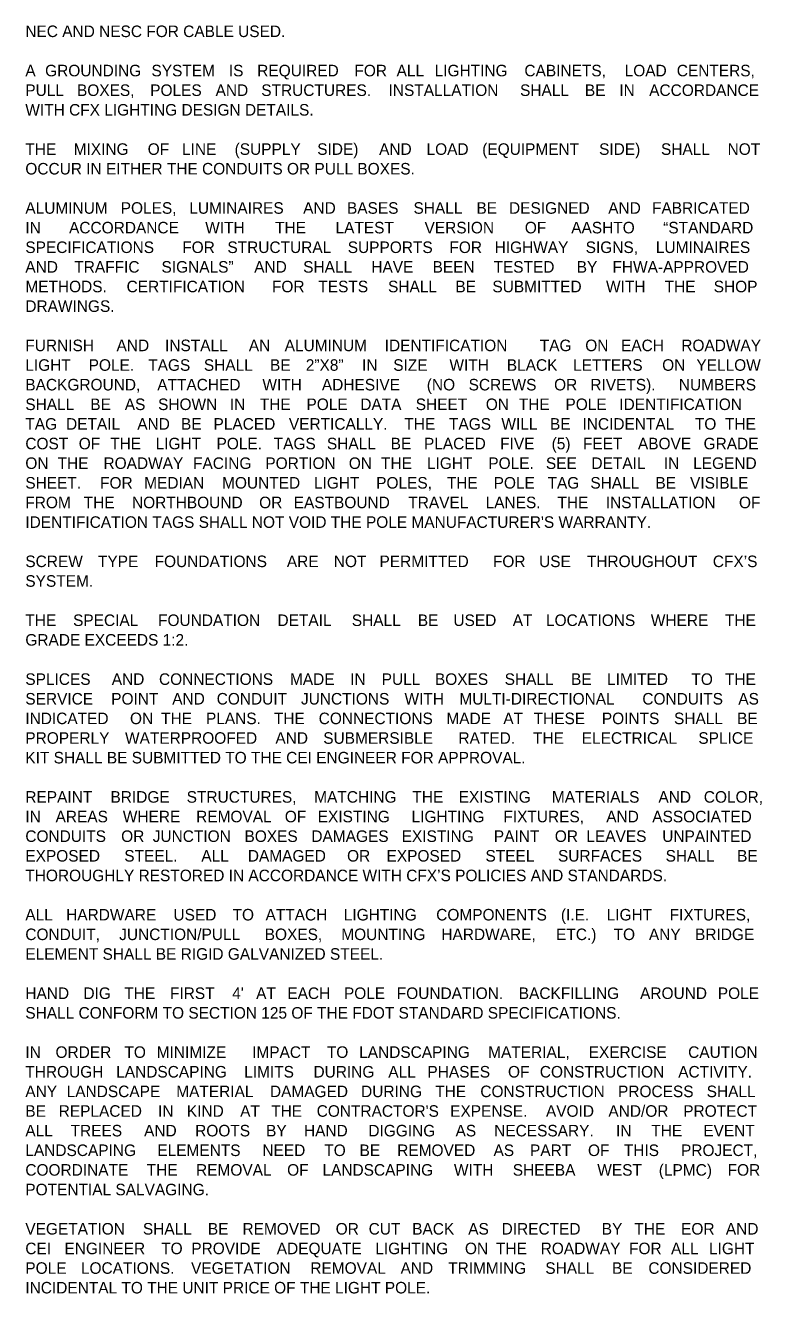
# Model space of a CAD drawing. Extents: x -55 to 2471539, y -90 to 3608906.
# Drawn here: x 568 to 1014, y 8 to 777 of the extents above; entities that cross this region are included whole.
import ezdxf

# ---------------------------------------------------------------- set-up
doc = ezdxf.new("R2010")
doc.units = 0
doc.layers.add('XSCell', color=7, linetype='Continuous')

msp = doc.modelspace()

# ---------------------------------------------------------------- texts
at = {"layer": 'XSCell'}
for s, p in [('NEC AND NESC FOR CABLE USED.', (568.01, 770.14)), ('GROUNDING ', (580.01, 746.34)), ('SYSTEM ', (644.47, 746.34)), ('IS ', (691.38, 746.34)), ('REQUIRED ', (708.58, 746.34)), ('FOR ', (767.49, 746.34)), ('LIGHTING ', (816.15, 746.34)), ('CABINETS, ', (870.55, 746.34)), ('LOAD ', (931.31, 746.34)), ('CENTERS, ', (962.92, 746.34)), ('A ', (568.01, 746.34)), ('ALL ', (793.05, 746.34)), ('PULL ', (568.01, 734.44)), ('BOXES, ', (599.32, 734.44)), ('POLES ', (643.71, 734.44)), ('AND ', (683.35, 734.44)), ('STRUCTURES. ', (711.03, 734.44)), ('INSTALLATION ', (788.2, 734.44)), ('SHALL ', (867.91, 734.44)), ('BE ', (907.21, 734.44)), ('IN ', (928.07, 734.44)), ('ACCORDANCE ', (946.18, 734.44)), ('WITH CFX LIGHTING DESIGN DETAILS.', (568.01, 722.54)), ('THE ', (568.01, 698.74)), ('MIXING ', (597.31, 698.74)), ('OF ', (642.19, 698.74)), ('LINE ', (663, 698.74)), ('(SUPPLY ', (694.88, 698.74)), ('SIDE) ', (744.95, 698.74)), ('AND ', (782.46, 698.74)), ('LOAD ', (811.22, 698.74)), ('(EQUIPMENT ', (844.96, 698.74)), ('SIDE) ', (915.82, 698.74)), ('SHALL ', (953.33, 698.74)), ('NOT ', (993.71, 698.74)), ('OCCUR IN EITHER THE CONDUITS OR PULL BOXES.', (568.01, 686.84)), ('ALUMINUM ', (568.01, 663.04)), ('POLES, ', (625.83, 663.04)), ('LUMINAIRES ', (667.41, 663.04)), ('AND ', (736.42, 663.04)), ('BASES ', (762.98, 663.04)), ('SHALL ', (803.29, 663.04)), ('BE ', (841.48, 663.04)), ('DESIGNED ', (861.21, 663.04)), ('AND ', (921.34, 663.04)), ('FABRICATED ', (947.9, 663.04)), ('IN ', (568.01, 651.14)), ('ACCORDANCE ', (594.51, 651.14)), ('WITH ', (677.06, 651.14)), ('THE ', (719.43, 651.14)), ('LATEST ', (756.05, 651.14)), ('VERSION ', (810.01, 651.14)), ('OF ', (870.8, 651.14)), ('AASHTO ', (898.93, 651.14)), ('“STANDARD ', (954.69, 651.14)), ('SPECIFICATIONS ', (568.01, 639.24)), ('FOR ', (663.12, 639.24)), ('STRUCTURAL ', (690.51, 639.24)), ('SUPPORTS ', (763.45, 639.24)), ('FOR ', (825.09, 639.24)), ('HIGHWAY ', (852.48, 639.24)), ('SIGNS, ', (907.69, 639.24)), ('LUMINAIRES ', (950.21, 639.24)), ('AND ', (568.01, 627.34)), ('TRAFFIC ', (597.7, 627.34)), ('SIGNALS” ', (650.56, 627.34)), ('AND ', (706.75, 627.34)), ('SHALL ', (736.44, 627.34)), ('HAVE ', (777.76, 627.34)), ('BEEN ', (814.87, 627.34)), ('TESTED ', (851.81, 627.34)), ('BY ', (902.26, 627.34)), ('FHWA-APPROVED ', (923.92, 627.34)), ('METHODS. ', (568.01, 615.44)), ('CERTIFICATION ', (629.39, 615.44)), ('FOR ', (717.5, 615.44)), ('TESTS ', (745.65, 615.44)), ('SHALL ', (787.89, 615.44)), ('BE ', (828.73, 615.44)), ('SUBMITTED ', (851.14, 615.44)), ('WITH ', (920.02, 615.44)), ('THE ', (955.54, 615.44)), ('SHOP ', (985.31, 615.44)), ('DRAWINGS.', (568.01, 603.54)), ('FURNISH ', (568.01, 579.74)), ('AND ', (623.29, 579.74)), ('INSTALL ', (652.69, 579.74)), ('AN ', (703.49, 579.74)), ('ALUMINUM ', (725.21, 579.74)), ('IDENTIFICATION ', (785.87, 579.74)), ('TAG ', (879.86, 579.74)), ('ON ', (907.43, 579.74)), ('EACH ', (929.1, 579.74)), ('ROADWAY ', (965.64, 579.74)), ('LIGHT ', (568.01, 567.84)), ('POLE. ', (606.39, 567.84)), ('TAGS ', (642.51, 567.84)), ('SHALL ', (676.24, 567.84)), ('BE ', (716.34, 567.84)), ('2”X8” ', (738.01, 567.84)), ('IN ', (772.11, 567.84)), ('SIZE ', (791.03, 567.84)), ('WITH ', (825.09, 567.84)), ('BLACK ', (859.87, 567.84)), ('LETTERS ', (900.07, 567.84)), ('ON ', (954.05, 567.84)), ('YELLOW ', (974.8, 567.84)), ('BACKGROUND, ', (568.01, 555.94)), ('ATTACHED ', (647.98, 555.94)), ('WITH ', (711.72, 555.94)), ('ADHESIVE ', (747.77, 555.94)), ('(NO ', (811.36, 555.94)), ('SCREWS ', (836.74, 555.94)), ('OR ', (888.54, 555.94)), ('RIVETS). ', (910.5, 555.94)), ('NUMBERS ', (964.15, 555.94)), ('SHALL ', (568.01, 544.04)), ('BE ', (607.37, 544.04)), ('AS ', (628.28, 544.04)), ('SHOWN ', (648.48, 544.04)), ('IN ', (691.99, 544.04)), ('THE ', (710.16, 544.04)), ('POLE ', (738.44, 544.04)), ('DATA ', (771.06, 544.04)), ('SHEET ', (804.66, 544.04)), ('ON ', (847.15, 544.04)), ('THE ', (867.16, 544.04)), ('POLE ', (895.44, 544.04)), ('IDENTIFICATION ', (928.06, 544.04)), ('TAG ', (568.01, 532.14)), ('DETAIL ', (592.69, 532.14)), ('AND ', (635.86, 532.14)), ('BE ', (662.38, 532.14)), ('PLACED ', (682.08, 532.14)), ('VERTICALLY. ', (727.77, 532.14)), ('THE ', (797.76, 532.14)), ('TAGS ', (824.83, 532.14)), ('WILL ', (856.59, 532.14)), ('BE ', (886.05, 532.14)), ('INCIDENTAL ', (905.75, 532.14)), ('TO ', (973.89, 532.14)), ('THE ', (992.12, 532.14)), ('COST ', (568.01, 520.24)), ('OF ', (600.37, 520.24)), ('THE ', (619.44, 520.24)), ('LIGHT ', (647, 520.24)), ('POLE. ', (683.91, 520.24)), ('TAGS ', (718.57, 520.24)), ('SHALL ', (750.83, 520.24)), ('BE ', (789.47, 520.24)), ('PLACED ', (809.66, 520.24)), ('FIVE ', (855.85, 520.24)), ('(5) ', (887.05, 520.24)), ('FEET ', (906.02, 520.24)), ('ABOVE ', (939.36, 520.24)), ('GRADE ', (979.17, 520.24)), ('ON ', (568.01, 508.34)), ('THE ', (587.57, 508.34)), ('ROADWAY ', (615.39, 508.34)), ('FACING ', (669.69, 508.34)), ('PORTION ', (713.51, 508.34)), ('ON ', (764.09, 508.34)), ('THE ', (783.65, 508.34)), ('LIGHT ', (811.48, 508.34)), ('POLE. ', (848.66, 508.34)), ('SEE ', (883.58, 508.34)), ('DETAIL ', (911.18, 508.34)), ('IN ', (955.12, 508.34)), ('LEGEND ', (972.84, 508.34)), ('SHEET. ', (568.01, 496.44)), ('FOR ', (613.33, 496.44)), ('MEDIAN ', (640.07, 496.44)), ('MOUNTED ', (687.27, 496.44)), ('LIGHT ', (742.99, 496.44)), ('POLES, ', (780.69, 496.44)), ('THE ', (823.52, 496.44)), ('POLE ', (851.88, 496.44)), ('TAG ', (884.57, 496.44)), ('SHALL ', (910.54, 496.44)), ('BE ', (949.98, 496.44)), ('VISIBLE ', (970.96, 496.44)), ('FROM ', (568.01, 484.54)), ('THE ', (603.39, 484.54)), ('NORTHBOUND ', (632.65, 484.54)), ('OR ', (709.75, 484.54)), ('EASTBOUND ', (730.69, 484.54)), ('TRAVEL ', (800.16, 484.54)), ('LANES. ', (847.03, 484.54)), ('THE ', (890.59, 484.54)), ('INSTALLATION ', (919.86, 484.54)), ('OF ', (1000.61, 484.54)), ("IDENTIFICATION TAGS SHALL NOT VOID THE POLE MANUFACTURER'S WARRANTY.", (568.01, 472.64)), ('SCREW ', (568.01, 448.84)), ('TYPE ', (612.05, 448.84)), ('FOUNDATIONS ', (646.38, 448.84)), ('ARE ', (726.54, 448.84)), ('NOT ', (755, 448.84)), ('PERMITTED ', (782.71, 448.84)), ('FOR ', (851.45, 448.84)), ('USE ', (879.44, 448.84)), ('THROUGHOUT ', (908.4, 448.84)), ('CFX’S ', (984.76, 448.84)), ('SYSTEM.', (568.01, 436.94)), ('THE ', (568.01, 413.14)), ('SPECIAL ', (596.95, 413.14)), ('FOUNDATION ', (648.45, 413.14)), ('DETAIL ', (720.86, 413.14)), ('SHALL ', (765.91, 413.14)), ('BE ', (805.93, 413.14)), ('USED ', (827.51, 413.14)), ('AT ', (863.48, 413.14)), ('LOCATIONS ', (883.63, 413.14)), ('WHERE ', (947.18, 413.14)), ('THE ', (992.12, 413.14)), ('GRADE EXCEEDS 1:2.', (568.01, 401.24)), ('SPLICES ', (568.01, 377.44)), ('AND ', (620.4, 377.44)), ('CONNECTIONS ', (649.03, 377.44)), ('MADE ', (728.42, 377.44)), ('IN ', (764.98, 377.44)), ('PULL ', (784.04, 377.44)), ('BOXES ', (816.31, 377.44)), ('SHALL ', (858.59, 377.44)), ('BE ', (898.84, 377.44)), ('LIMITED ', (920.65, 377.44)), ('TO ', (971.78, 377.44)), ('THE ', (992.12, 377.44)), ('SERVICE ', (568.01, 365.54)), ('POINT ', (620.07, 365.54)), ('AND ', (657.06, 365.54)), ('CONDUIT ', (684.01, 365.54)), ('JUNCTIONS ', (735.09, 365.54)), ('WITH ', (797.86, 365.54)), ('MULTI-DIRECTIONAL ', (831.11, 365.54)), ('CONDUITS ', (942.04, 365.54)), ('AS ', (1000.2, 365.54)), ('INDICATED ', (568.01, 353.64)), ('ON ', (631.45, 353.64)), ('THE ', (650.33, 353.64)), ('PLANS. ', (677.5, 353.64)), ('THE ', (718.68, 353.64)), ('CONNECTIONS ', (745.84, 353.64)), ('MADE ', (823.22, 353.64)), ('AT ', (857.76, 353.64)), ('THESE ', (876.13, 353.64)), ('POINTS ', (917.5, 353.64)), ('SHALL ', (961.24, 353.64)), ('BE ', (999.48, 353.64)), ('PROPERLY ', (568.01, 341.74)), ('WATERPROOFED ', (628.45, 341.74)), ('AND ', (719.6, 341.74)), ('SUBMERSIBLE ', (748.61, 341.74)), ('RATED. ', (830.55, 341.74)), ('THE ', (875.77, 341.74)), ('ELECTRICAL ', (905.32, 341.74)), ('SPLICE ', (975.98, 341.74)), ('KIT SHALL BE SUBMITTED TO THE CEI ENGINEER FOR APPROVAL.', (568.01, 329.84)), ('REPAINT ', (568.01, 306.04)), ('BRIDGE ', (619.62, 306.04)), ('STRUCTURES, ', (665.82, 306.04)), ('MATCHING ', (743.13, 306.04)), ('THE ', (802.64, 306.04)), ('EXISTING ', (830.7, 306.04)), ('MATERIALS ', (887.2, 306.04)), ('AND ', (951.78, 306.04)), ('COLOR, ', (979.3, 306.04)), ('IN ', (568.01, 294.14)), ('AREAS ', (586.33, 294.14)), ('WHERE ', (627.11, 294.14)), ('REMOVAL ', (671.54, 294.14)), ('OF ', (725.3, 294.14)), ('EXISTING ', (745.24, 294.14)), ('LIGHTING ', (802.12, 294.14)), ('FIXTURES, ', (857.79, 294.14)), ('AND ', (920.15, 294.14)), ('ASSOCIATED ', (948.05, 294.14)), ('CONDUITS ', (568.01, 282.24)), ('OR ', (626.11, 282.24)), ('JUNCTION ', (645.22, 282.24)), ('BOXES ', (700.86, 282.24)), ('DAMAGES ', (741.4, 282.24)), ('EXISTING ', (796.13, 282.24)), ('PAINT ', (852.01, 282.24)), ('OR ', (888.99, 282.24)), ('LEAVES ', (908.1, 282.24)), ('UNPAINTED ', (954.1, 282.24)), ('EXPOSED ', (568.01, 270.34)), ('STEEL. ', (627.98, 270.34)), ('ALL ', (674.69, 270.34)), ('DAMAGED ', (702.88, 270.34)), ('OR ', (763.04, 270.34)), ('EXPOSED ', (786.96, 270.34)), ('STEEL ', (846.94, 270.34)), ('SURFACES ', (890.89, 270.34)), ('SHALL ', (956.14, 270.34)), ('BE ', (999.48, 270.34)), ('THOROUGHLY RESTORED IN ACCORDANCE WITH CFX’S POLICIES AND STANDARDS. ', (568.01, 258.44)), ('ALL ', (568.01, 234.64)), ('HARDWARE ', (592.75, 234.64)), ('USED ', (657.8, 234.64)), ('TO ', (693.63, 234.64)), ('ATTACH ', (713.61, 234.64)), ('LIGHTING ', (761.04, 234.64)), ('COMPONENTS ', (817.08, 234.64)), ('(I.E. ', (892.66, 234.64)), ('LIGHT ', (920.42, 234.64)), ('FIXTURES, ', (958.58, 234.64)), ('CONDUIT, ', (568.01, 222.74)), ('JUNCTION/PULL ', (624.91, 222.74)), ('BOXES, ', (713.12, 222.74)), ('MOUNTING ', (759.53, 222.74)), ('HARDWARE, ', (820.2, 222.74)), ('ETC.) ', (889.76, 222.74)), ('TO ', (924.61, 222.74)), ('ANY ', (946.03, 222.74)), ('BRIDGE ', (973.98, 222.74)), ('ELEMENT SHALL BE RIGID GALVANIZED STEEL.', (568.01, 210.84)), ('HAND ', (568.01, 187.04)), ('DIG ', (603.24, 187.04)), ('THE ', (627.99, 187.04)), ('FIRST ', (655.69, 187.04)), ("4' ", (693.4, 187.04)), ('AT ', (707.92, 187.04)), ('EACH ', (726.83, 187.04)), ('POLE ', (761.14, 187.04)), ('FOUNDATION. ', (793.18, 187.04)), ('BACKFILLING ', (867.11, 187.04)), ('AROUND ', (940.66, 187.04)), ('POLE ', (987.78, 187.04)), ('SHALL CONFORM TO SECTION 125 OF THE FDOT STANDARD SPECIFICATIONS.', (568.01, 175.14)), ('IN ', (568.01, 151.34)), ('ORDER ', (586.31, 151.34)), ('TO ', (628.08, 151.34)), ('MINIMIZE ', (647.66, 151.34)), ('IMPACT ', (705.48, 151.34)), ('TO ', (750.79, 151.34)), ('LANDSCAPING ', (770.36, 151.34)), ('MATERIAL, ', (848.58, 151.34)), ('EXERCISE ', (909.49, 151.34)), ('CAUTION ', (969.8, 151.34)), ('THROUGH ', (568.01, 139.44)), ('LANDSCAPING ', (623.09, 139.44)), ('LIMITS ', (700.68, 139.44)), ('DURING ', (742.68, 139.44)), ('ALL ', (788.03, 139.44)), ('PHASES ', (811.75, 139.44)), ('OF ', (860.6, 139.44)), ('CONSTRUCTION ', (879.89, 139.44)), ('ACTIVITY. ', (963.78, 139.44)), ('ANY ', (568.01, 127.54)), ('LANDSCAPE ', (593.07, 127.54)), ('MATERIAL ', (659.49, 127.54)), ('DAMAGED ', (716.29, 127.54)), ('DURING ', (771.54, 127.54)), ('THE ', (816.47, 127.54)), ('CONSTRUCTION ', (843.83, 127.54)), ('PROCESS ', (927.29, 127.54)), ('SHALL ', (981.03, 127.54)), ('BE ', (568.01, 115.64)), ('REPLACED ', (588.23, 115.64)), ('IN ', (648.46, 115.64)), ('KIND ', (665.93, 115.64)), ('AT ', (698.24, 115.64)), ('THE ', (717.04, 115.64)), ("CONTRACTOR'S ", (744.63, 115.64)), ('EXPENSE. ', (825.54, 115.64)), ('AVOID ', (883.61, 115.64)), ('AND/OR ', (921.45, 115.64)), ('PROTECT ', (966.83, 115.64)), ('ALL ', (568.01, 103.74)), ('TREES ', (595.45, 103.74)), ('AND ', (639.99, 103.74)), ('ROOTS ', (670.96, 103.74)), ('BY ', (713.96, 103.74)), ('HAND ', (736.91, 103.74)), ('DIGGING ', (775.95, 103.74)), ('AS ', (828.8, 103.74)), ('NECESSARY. ', (852.22, 103.74)), ('IN ', (926.06, 103.74)), ('THE ', (947.46, 103.74)), ('EVENT ', (978.98, 103.74)), ('LANDSCAPING ', (568.01, 91.84)), ('ELEMENTS ', (648.02, 91.84)), ('NEED ', (711.71, 91.84)), ('TO ', (749.23, 91.84)), ('BE ', (770.6, 91.84)), ('REMOVED ', (793.44, 91.84)), ('AS ', (851.82, 91.84)), ('PART ', (873.94, 91.84)), ('OF ', (909.09, 91.84)), ('THIS ', (930.81, 91.84)), ('PROJECT, ', (965.48, 91.84)), ('COORDINATE ', (568.01, 79.94)), ('THE ', (641.59, 79.94)), ('REMOVAL ', (671.49, 79.94)), ('OF ', (726.72, 79.94)), ('LANDSCAPING ', (748.13, 79.94)), ('WITH ', (827.84, 79.94)), ('SHEEBA ', (863.49, 79.94)), ('WEST ', (914.73, 79.94)), ('(LPMC) ', (951.99, 79.94)), ('FOR ', (993.73, 79.94)), ('POTENTIAL SALVAGING.', (568.01, 68.04)), ('VEGETATION ', (568.01, 44.24)), ('SHALL ', (639.27, 44.24)), ('BE ', (678.67, 44.24)), ('REMOVED ', (699.63, 44.24)), ('OR ', (756.14, 44.24)), ('CUT ', (776.13, 44.24)), ('BACK ', (802.52, 44.24)), ('AS ', (836.47, 44.24)), ('DIRECTED ', (856.71, 44.24)), ('BY ', (917.44, 44.24)), ('THE ', (937.2, 44.24)), ('EOR ', (965.52, 44.24)), ('AND ', (992.65, 44.24)), ('CEI ', (568.01, 32.34)), ('ENGINEER ', (591.75, 32.34)), ('TO ', (650.35, 32.34)), ('PROVIDE ', (668.61, 32.34)), ('ADEQUATE ', (720.42, 32.34)), ('LIGHTING ', (780.17, 32.34)), ('ON ', (834.49, 32.34)), ('THE ', (853.31, 32.34)), ('ROADWAY ', (880.4, 32.34)), ('FOR ', (933.96, 32.34)), ('ALL ', (959.44, 32.34)), ('LIGHT ', (982.46, 32.34)), ('POLE ', (568.01, 20.44)), ('LOCATIONS. ', (601.72, 20.44)), ('VEGETATION ', (668.47, 20.44)), ('REMOVAL ', (740.78, 20.44)), ('AND ', (795.48, 20.44)), ('TRIMMING ', (824.32, 20.44)), ('SHALL ', (883.22, 20.44)), ('BE ', (923.68, 20.44)), ('CONSIDERED ', (945.69, 20.44)), ('INCIDENTAL TO THE UNIT PRICE OF THE LIGHT POLE.', (568.01, 8.54))]:
    msp.add_text(s, height=7, dxfattribs=at).set_placement(p)

doc.saveas('drawing.dxf')
